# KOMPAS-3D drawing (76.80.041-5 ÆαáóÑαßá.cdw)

Views: Вид 1, Вид 2, Вид 3
Referenced files in C:\Users\ptitsin\Desktop\Блок ПД 476 (160т)\: 76.80.041-5 Траверса.cdw
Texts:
  36...40 HRC.
  H14, h14,  IT 14/2.
  Острые кромки притупить фаской 1х45 .
  Ra 6,3
  Ra 6,3 ( )
  ACAD_ISO02W100_RGB_0_0_0_SC_0.5_THICK_-0.03
  ACAD_ISO02W100_RGB_0_0_0_SC_0.5_THICK_0.18
  GOST2.303 5_RGB_255_0_0_SC_0.3_THICK_0.25
  ACAD_ISO02W100_RGB_0_0_0_SC_0.3_THICK_-0.03
  GOST4_RGB_0_0_255_SC_1_THICK_0.25
  ACAD_ISO10W100_RGB_0_0_0_SC_1_THICK_-0.03
  ACAD_ISO10W100_RGB_0_0_0_SC_1_THICK_0.18
  ACAD_ISO02W100_RGB_0_0_0_SC_0.3_THICK_0.18
  GOST2.303 5_RGB_0_0_255_SC_1_THICK_0.25
  GOST2.303 5_RGB_255_0_0_SC_1_THICK_0.25
  Траверса
  Сталь 45 ГОСТ 1050-88
Dimensions and other numbers on the sheet: 10; 190; 25; 80; 50; 150; 230; 35; 110; 40; 60; 22; 5; 115; 20; 6,2; 26; 16; 0,02; 8 отв.; 0,8; 70; 4 отв.; 3 отв.; 4; 1:1; 1; 76.80.041-5; 76.80.041-5-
